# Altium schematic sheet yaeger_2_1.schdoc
size 127 x 101 mm
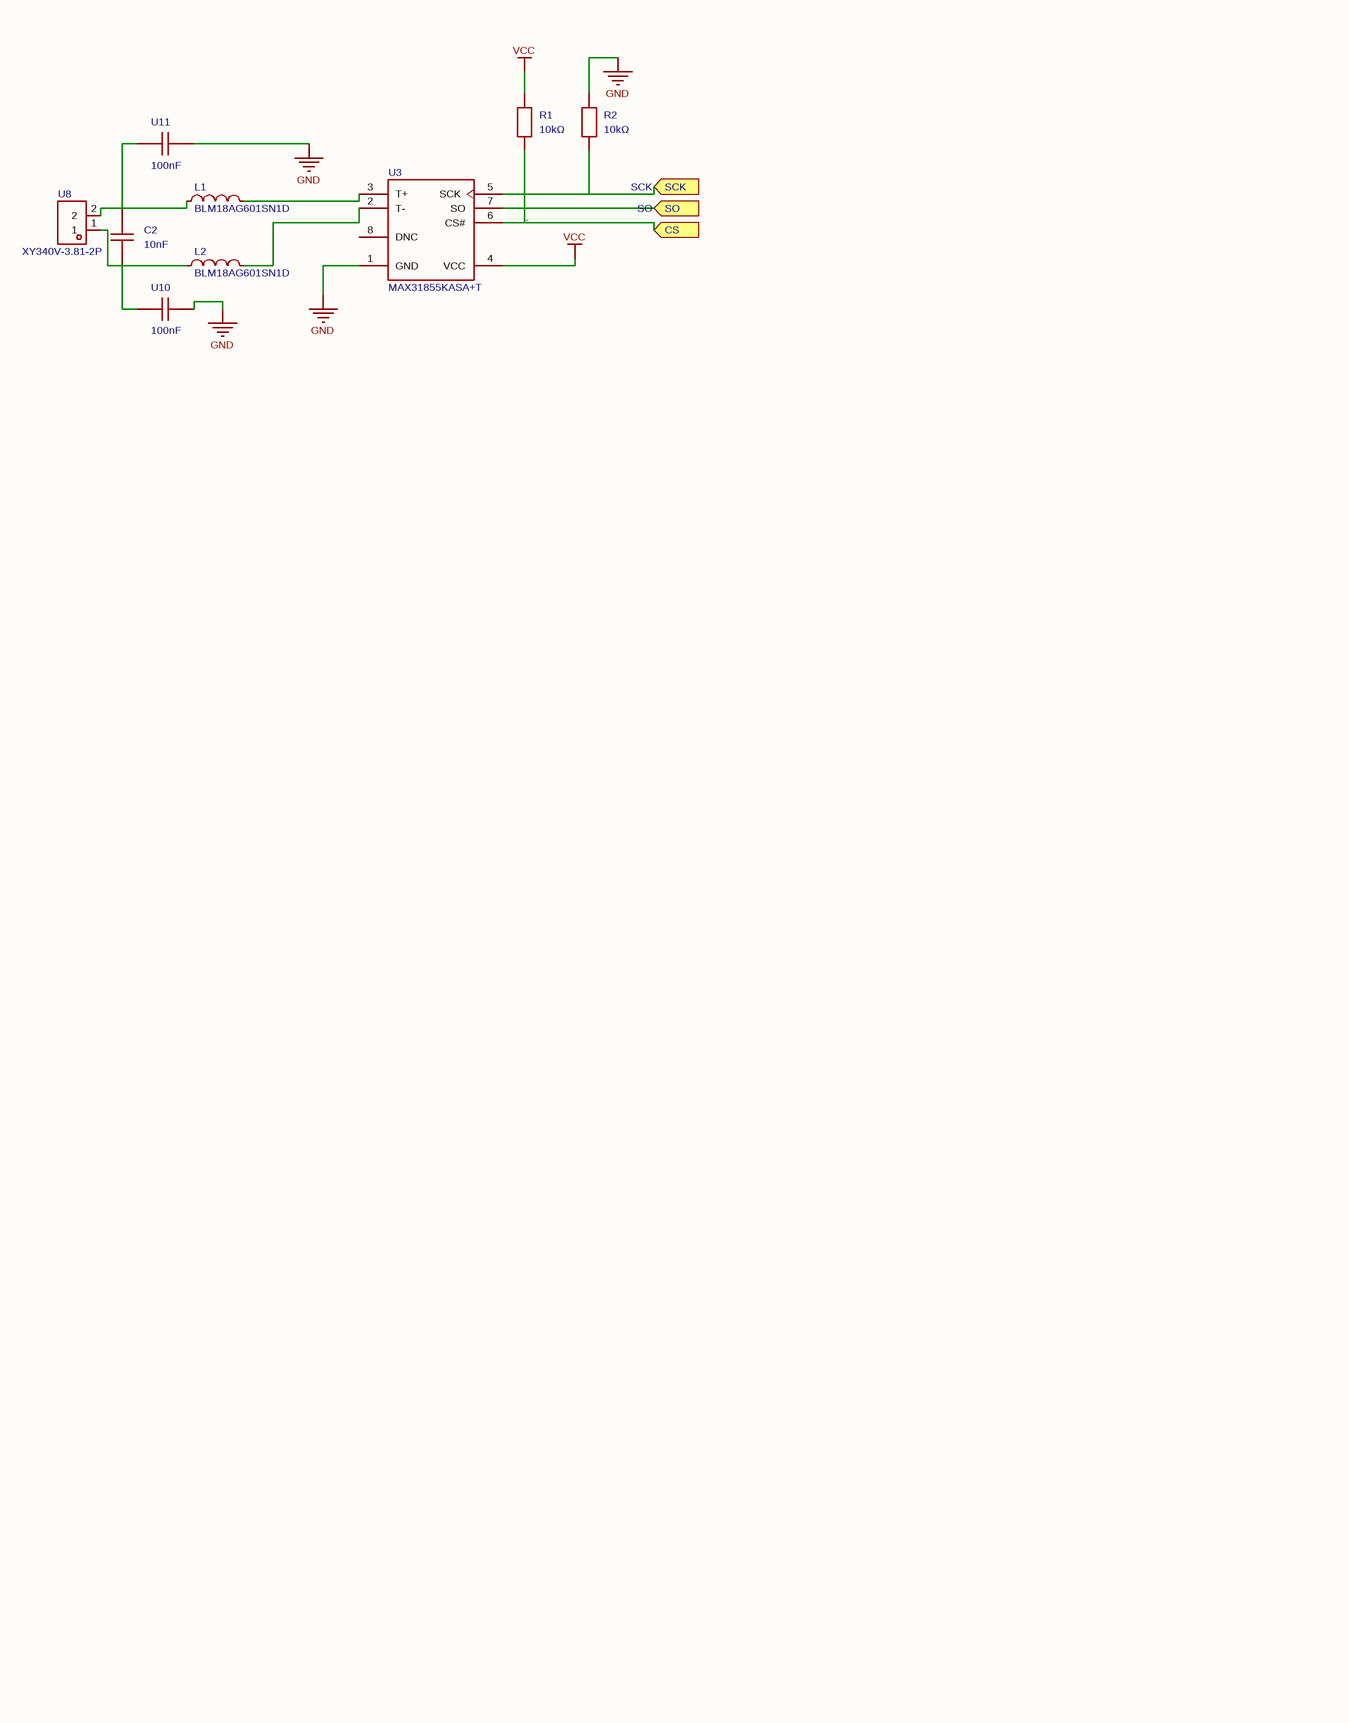
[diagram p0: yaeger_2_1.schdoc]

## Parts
C2  10nF  [C0603]
L1  BLM18AG601SN1D  [L0603]
L2  BLM18AG601SN1D  [L0603]
R1  10kΩ  [R0603]
R2  10kΩ  [R0603]
U3  MAX31855KASA+T  [SO-8_L4.9-W3.9-P1.27-LS5.9-BL]
U8  XY340V-3.81-2P  [CONN-TH_XY340V-3.81-2P]
U10  100nF  [C0603]
U11  100nF  [C0603]

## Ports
CS (in), SCK (in), SO (in)

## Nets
GND: R2.2 U3.1(GND) U10.2 U11.2
VCC: R1.2 U3.4(VCC)
N$2: R1.1 U3.6(CS#) ; port CS
SCK: R2.1 U3.5(SCK) ; port SCK
SO: U3.7(SO) ; port SO
NetC2_1: C2.1 L2.1 U8.1 U10.1
NetC2_2: C2.2 L1.1 U8.2 U11.1
NetL1_2: L1.2 U3.3(T+)
NetL2_2: L2.2 U3.2(T-)

Not connected (* = marked no-connect by the designer): U3 8(DNC)

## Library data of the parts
C2 = C0603X103K025T: Capacitance:10nF Tolerance:±10% Tolerance:±10% Voltage Rating:25V Temperature Coefficient:-; Manufacturer: IHHEC(禾伸堂); AddInBom: yes; ModelId: 624118aa3cc7497086c383c2d72e08520819f05c4eef4c71ace90d822a990e87; ModelName: C0603_L1.6-W0.8-H0.8; ModelTransform: 62.992,31.496,0,0,0,0,0,0,0; Tolerance: ±10%; Voltage Rating: 25V
L1 L2 = BLM18AG601SN1D: Impedance @ Frequency:600Ω@100MHz Tolerance:±25% Tolerance:±25% DC Resistance(DCR):380mΩ Current Rating:500mA Number of Circuits:1 Operating Temperature:-55℃~+125℃ Operating Temperature:-55℃~+125℃; Manufacturer: muRata(村田); AddInBom: yes; ModelId: ece81e7160a84e0c9a4133ba5d41d18a0819f05c4eef4c71ace90d822a990e87; ModelName: L0603_L1.6-W0.8-H0.5_BEAD; ModelTransform: 62.992,31.496,0,180,0,0,0.094,0.629,0; Tolerance: ±25%; DC Resistance(DCR): 380mΩ; Current Rating: 500mA; Number of Circuits: 1
R1 R2 = SCR0603J10K: Type:Thick Film Resistors Resistance: Tolerance:±5% Tolerance:±5% Power(Watts): Overload Voltage (Max): Operating Temperature Range:-55℃~+155℃ Operating Temperature Range:-55℃~+155℃; Manufacturer: VO(翔胜); AddInBom: yes; ModelId: 112863783b5b41f1b5254f87eedc79320819f05c4eef4c71ace90d822a990e87; ModelTransform: 31.8897,63.7794,0,90,0,0,0,0,0; Tolerance: ±5%
U3 = MAX31855KASA+T: Resolution (Bits):14 Number of Channels:- Voltage - Supply:3V~3.6V Voltage - Supply:3V~3.6V Interface Type:SPI The Chip Type:Thermocouple-to-Digital Converter Operating Temperature:-40℃~+125℃ Operating Temperature:-40℃~+125℃ Sampling Rate:- Quiescent Curr; Manufacturer: ADI(亚德诺)/MAXIM(美信); AddInBom: yes; ModelId: 548305ef4d1f4879a4f47128885951540819f05c4eef4c71ace90d822a990e87; ModelName: SO-8_L4.9-W3.9-H1.5-LS5.9-P1.27; ModelTransform: 240.39054,192.913,0,270,0,0,0.0005,-0.0005,0; Resolution (Bits): 14; Interface Type: SPI; Quiescent Current (Iq): 1500uA
U8 = XY340V-3.81-2P: Number of Positions or Pins:1x2P Pitch:3.81mm Color:Green Mounting Type:Through Hole Number of Pins:2P Number of Rows:1 Number of PINs Per Row:2 Screw Specification:M2 Current Rating:7A Voltage Rating (Max):300V Wire Gauge - AWG:18~24 Wire Gauge - mm2:1 W; Manufacturer: XINLAIYA(新莱亚); AddInBom: yes; ModelId: 4ef887ec1e2e4a95b008f9208d1cbdb50819f05c4eef4c71ace90d822a990e87; ModelTransform: 331.4954,279.527,0,0,0,0,0,-18.307,-137.795; Number of Positions or Pins: 1x2P; Pitch: 3.81mm; Number of PINs Per Row: 2; Screw Specification: M2; Current Rating: 7A; Voltage Rating (Max): 300V; Wire Gauge - AWG: 18~24; Wire Gauge - mm2: 1
U10 U11 = 0603Y0160104JDR: Capacitance:100nF Tolerance:±5% Tolerance:±5% Voltage Rating:16V Temperature Coefficient:-; Manufacturer: Knowles(楼氏); AddInBom: yes; ModelId: 624118aa3cc7497086c383c2d72e08520819f05c4eef4c71ace90d822a990e87; ModelName: C0603_L1.6-W0.8-H0.8; ModelTransform: 62.992,31.496,0,0,0,0,0,0,0; Tolerance: ±5%; Voltage Rating: 16V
